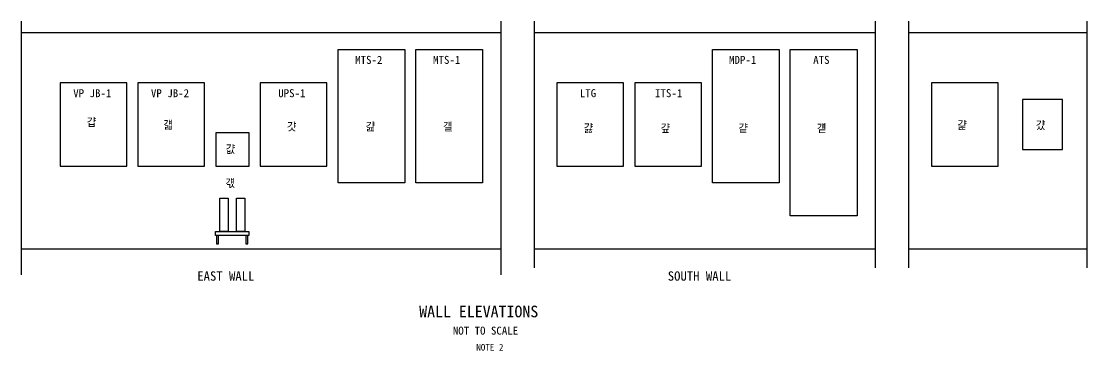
# Model space of a CAD drawing. Extents: x 0 to 31.9, y -2.3 to 7.6.
import ezdxf

# ---------------------------------------------------------------- set-up
doc = ezdxf.new("R2010")
doc.units = 0
for name, color, linetype in [('HS_Title', 7, 'Continuous'), ('Sheets_General Details - Sheet Number Text', 7, 'Continuous'), ('Sheets_General Details - Version Text', 7, 'Continuous')]:
    doc.layers.add(name, color=color, linetype=linetype)

msp = doc.modelspace()

# ---------------------------------------------------------------- linework, layer by layer
at = {"layer": 'Sheets_General Details - Version Text'}
for p, q in [((0, 7.617), (0, 0)), ((14.379, 7.617), (14.379, 0)), ((15.379, 7.617), (15.379, 0.214)), ((25.608, 7.617), (25.608, 0.214)), ((26.608, 7.617), (26.608, 0.214)), ((31.947, 7.617), (31.947, 0.214)), ((14.379, 7.269), (0, 7.269)), ((25.608, 7.269), (15.379, 7.269)), ((31.947, 7.269), (26.608, 7.269)), ((14.379, 0.769), (0, 0.769)), ((25.608, 0.769), (15.379, 0.769)), ((31.947, 0.769), (26.608, 0.769))]:
    msp.add_line(p, q, dxfattribs=at)
for points in [[(9.497, 6.769), (11.497, 6.769), (11.497, 2.769), (9.497, 2.769)], [(11.83, 6.769), (13.83, 6.769), (13.83, 2.769), (11.83, 2.769)], [(20.726, 6.769), (22.726, 6.769), (22.726, 2.769), (20.726, 2.769)], [(23.06, 6.769), (25.06, 6.769), (25.06, 1.769), (23.06, 1.769)], [(1.164, 3.269), (3.164, 3.269), (3.164, 5.769), (1.164, 5.769)], [(3.497, 3.269), (5.497, 3.269), (5.497, 5.769), (3.497, 5.769)], [(7.164, 3.269), (9.164, 3.269), (9.164, 5.769), (7.164, 5.769)], [(16.06, 3.269), (18.06, 3.269), (18.06, 5.769), (16.06, 5.769)], [(18.393, 3.269), (20.393, 3.269), (20.393, 5.769), (18.393, 5.769)], [(27.289, 3.269), (29.289, 3.269), (29.289, 5.769), (27.289, 5.769)], [(30.022, 3.769), (31.222, 3.769), (31.222, 5.269), (30.022, 5.269)], [(5.83, 3.269), (6.83, 3.269), (6.83, 4.269), (5.83, 4.269)], [(6.202, 1.306), (5.952, 1.306), (5.952, 2.306), (6.202, 2.306)], [(6.702, 1.306), (6.452, 1.306), (6.452, 2.306), (6.702, 2.306)], [(5.827, 1.306), (6.827, 1.306), (6.827, 1.181), (5.827, 1.181)], [(5.917, 1.181), (5.857, 1.181), (5.857, 0.931), (5.917, 0.931)], [(6.797, 1.181), (6.737, 1.181), (6.737, 0.931), (6.797, 0.931)]]:
    msp.add_lwpolyline(points, close=True, dxfattribs=at)

# ---------------------------------------------------------------- texts
at = {"layer": 'HS_Title'}
for s, p in [('걉', (1.963, 4.466)), ('걟', (4.257, 4.388)), ('걋', (7.966, 4.333)), ('걆', (10.328, 4.333)), ('걜', (12.646, 4.333)), ('걇', (16.868, 4.283)), ('걒', (19.169, 4.285)), ('걑', (21.501, 4.283)), ('걛', (23.856, 4.283)), ('걅', (28.069, 4.376)), ('걌', (30.422, 4.374)), ('걊', (6.128, 3.656)), ('걗', (6.119, 2.636))]:
    msp.add_text(s, height=0.24, dxfattribs=at).set_placement(p)
at = {"layer": 'Sheets_General Details - Sheet Number Text'}
for s, height, p in [('MTS-2', 0.24, (10.011, 6.337)), ('MTS-1', 0.24, (12.348, 6.337)), ('MDP-1', 0.24, (21.223, 6.337)), ('ATS', 0.24, (23.746, 6.337)), ('VP JB-1', 0.24, (1.557, 5.337)), ('VP JB-2', 0.24, (3.887, 5.337)), ('UPS-1', 0.24, (7.704, 5.337)), ('LTG', 0.24, (16.748, 5.337)), ('ITS-1', 0.24, (19.003, 5.337)), ('EAST WALL', 0.28, (5.276, -0.175)), ('SOUTH WALL', 0.28, (19.385, -0.175)), ('WALL ELEVATIONS', 0.35, (11.931, -1.275)), ('NOT TO SCALE', 0.24, (12.94, -1.795)), ('NOTE 2', 0.2, (13.642, -2.275))]:
    msp.add_text(s, height=height, dxfattribs=at).set_placement(p)

doc.saveas('drawing.dxf')
